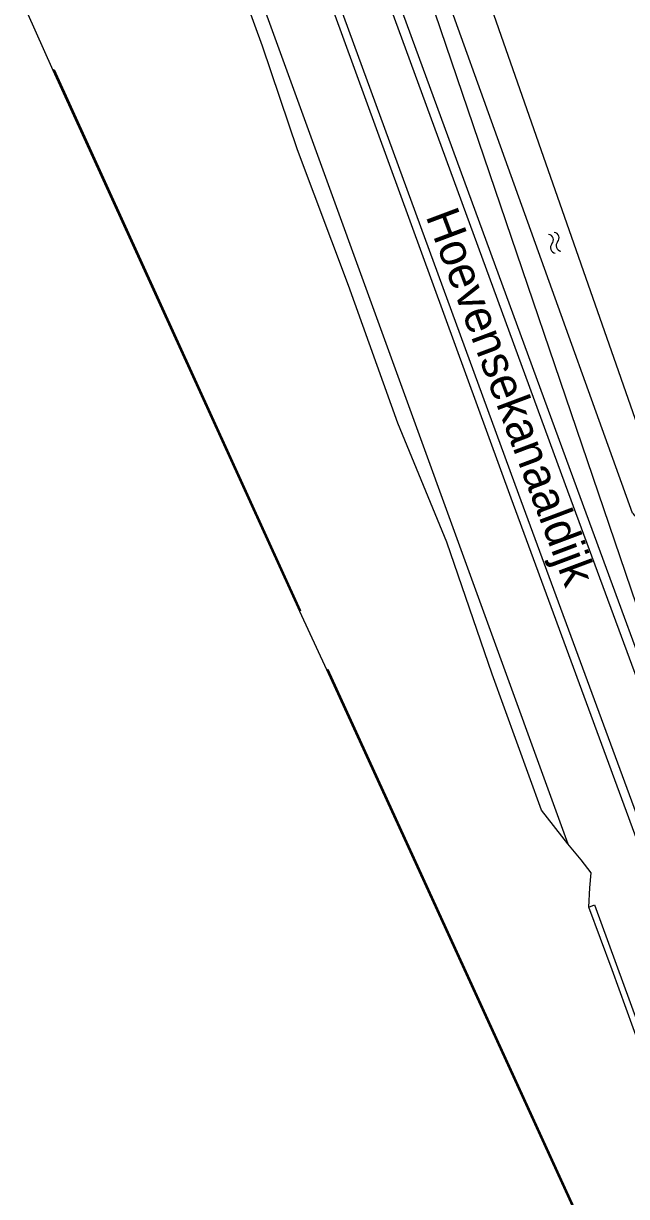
# Model space of a CAD drawing. Extents: x 135990 to 139000, y 393500 to 396000.
# Drawn here: x 136300.2 to 136345.5, y 395403.6 to 395491.8 of the extents above; entities that cross this region are included whole.
import ezdxf

# ---------------------------------------------------------------- set-up
doc = ezdxf.new("R2010")
doc.units = 0
for name, color, linetype in [('gg-afsc-muur', 7, 'Continuous'), ('gg-anno-openbare ruimte label', 7, 'Continuous'), ('gg-knt-bovenkant onderkant talud', 7, 'Continuous'), ('gg-knt-verharding', 7, 'Continuous'), ('gg-knt-verharding nz', 7, 'Continuous'), ('gg-kntw-beschoeiing', 7, 'Continuous'), ('gg-kntw-bovenkant insteek waterloop', 7, 'Continuous'), ('gt-symb-watersymbool', 7, 'Continuous'), ('gx-grn-maaiveld', 7, 'Continuous')]:
    doc.layers.add(name, color=color, linetype=linetype)

# ---------------------------------------------------------------- blocks, each defined once
blk = doc.blocks.new('gt0-WA')
at = {"layer": 'gt-symb-watersymbool'}
for centre, start, end in [((-0.323, 0.022), 28.07249, 151.92751), ((0.427, 0.422), 208.07248, 331.92751), ((-0.323, -0.428), 28.07249, 151.92751), ((0.427, -0.028), 208.07248, 331.92751)]:
    blk.add_arc(centre, 0.425, start, end, dxfattribs=at)

msp = doc.modelspace()

# ---------------------------------------------------------------- linework, layer by layer
at = {"layer": 'gg-afsc-muur'}
for p, q in [((136320.937, 395447.619), (136302.417, 395488.297)), ((136342.152, 395401.33), (136322.977, 395443.213))]:
    msp.add_line(p, q, dxfattribs=at)
at = {"layer": 'gg-knt-bovenkant onderkant talud'}
msp.add_line((136350.492, 395435.501), (136328.239, 395500.996), dxfattribs=at)
at = {"layer": 'gg-knt-verharding'}
msp.add_lwpolyline([(136352.995, 395412.189), (136350.623, 395418.556), (136336.812, 395456.09), (136321.736, 395497.501)], dxfattribs=at)
at = {"layer": 'gg-knt-verharding nz'}
msp.add_lwpolyline([(136353.461, 395412.751), (136351.209, 395418.825), (136337.397, 395456.352), (136322.276, 395497.682), (136320.876, 395501.389), (136319.312, 395505.03), (136317.587, 395508.598), (136315.706, 395512.086), (136313.671, 395515.486), (136311.487, 395518.793), (136309.158, 395521.999), (136306.688, 395525.098), (136294.38, 395539.551), (136287.61, 395548.271), (136281.312, 395557.336), (136275.502, 395566.723), (136270.198, 395576.404), (136267.599, 395581.673), (136265.152, 395587.015), (136262.859, 395592.424), (136260.721, 395597.896), (136257.4, 395606.872), (136256.678, 395608.894)], dxfattribs=at)
at = {"layer": 'gg-kntw-beschoeiing'}
msp.add_lwpolyline([(136274.448, 395550.333), (136314.52, 395503.22), (136341.063, 395430.103)], dxfattribs=at)
msp.add_lwpolyline([(136274.448, 395550.333), (136314.52, 395503.22), (136341.063, 395430.103)], dxfattribs=at)
at = {"layer": 'gg-kntw-bovenkant insteek waterloop'}
for points in [[(136345.929, 395454.948), (136329.74, 395500), (136322.995, 395518.327), (136326.098, 395518.895)], [(136345.929, 395454.948), (136353.66, 395445.964), (136348.078, 395456.484), (136332.89, 395500), (136326.098, 395518.895)]]:
    msp.add_lwpolyline(points, dxfattribs=at)
at = {"layer": 'gx-grn-maaiveld'}
for p, q in [((136300.379, 395492.695), (136302.371, 395488.276)), ((136302.371, 395488.276), (136302.417, 395488.297)), ((136302.371, 395488.276), (136320.892, 395447.598)), ((136320.937, 395447.619), (136320.892, 395447.598)), ((136320.892, 395447.598), (136322.932, 395443.192)), ((136322.932, 395443.192), (136322.977, 395443.213))]:
    msp.add_line(p, q, dxfattribs=at)
for points in [[(136290.397, 395550.373), (136293.705, 395546.009), (136297.133, 395541.739), (136309.424, 395527.284), (136311.945, 395524.154), (136314.324, 395520.914), (136316.554, 395517.571), (136318.633, 395514.131), (136320.555, 395510.601), (136322.316, 395506.989), (136323.914, 395503.301), (136325.345, 395499.545), (136340.872, 395457.111), (136356.069, 395415.897)], [(136341.063, 395430.103), (136339.079, 395432.633), (136335.39, 395442.865), (136331.968, 395452.79), (136328.306, 395461.729), (136324.582, 395472.084), (136320.745, 395482.286), (136318.122, 395490.081), (136316.187, 395495.386), (136313.87, 395498.785), (136311.404, 395501.695), (136307.678, 395506.736), (136301.422, 395514.874), (136293.739, 395524.426), (136286.851, 395533.159), (136283.002, 395538.433), (136282.258, 395538.752), (136281.513, 395538.353), (136280.341, 395537.648)], [(136356.062, 395419.371), (136355.316, 395420.133), (136349.733, 395435.116), (136341.542, 395457.404), (136326.167, 395499.429)], [(136302.417, 395488.297), (136302.463, 395488.318), (136320.983, 395447.64), (136320.937, 395447.619)], [(136322.932, 395443.192), (136342.106, 395401.309), (136342.145, 395401.238)], [(136322.977, 395443.213), (136323.023, 395443.234), (136342.229, 395401.269)], [(136342.658, 395425.341), (136342.724, 395426.794), (136342.818, 395427.911), (136342.06, 395428.902), (136341.063, 395430.103)], [(136342.658, 395425.341), (136343.078, 395425.502), (136349.479, 395407.948)], [(136349.143, 395407.542), (136344.409, 395420.612), (136342.658, 395425.341)]]:
    msp.add_lwpolyline(points, dxfattribs=at)

# ---------------------------------------------------------------- block references
at = {"layer": 'gt-symb-watersymbool', "rotation": -70.73158503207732}
msp.add_blockref('gt0-WA', (136340.072, 395475.341), dxfattribs=at)

# ---------------------------------------------------------------- texts
at = {"layer": 'gg-anno-openbare ruimte label'}
msp.add_text('Hoevensekanaaldijk', height=2.5, rotation=290.6, dxfattribs=at).set_placement((136330.366, 395477.298))

doc.saveas('drawing.dxf')
